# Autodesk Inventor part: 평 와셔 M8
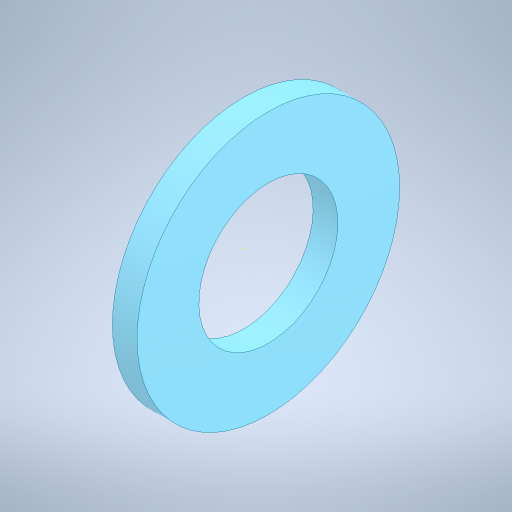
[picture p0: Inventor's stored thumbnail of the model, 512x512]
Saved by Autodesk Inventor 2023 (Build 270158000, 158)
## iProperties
Created: 2025-10
Part Number: 평 와셔 M8
Material: 강철, 연강
Description: 평면 와셔
Document SubType Name: Modeling
Designer: home
Density: 7.85 g/cm^3
Appearance: 기본값
Author: jhkim
Sending System: Autodesk Inventor 2026
Preprocessor: ST-DEVELOPER v20.1
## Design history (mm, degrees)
sketch "스케치1"
  geometry: 1 further point
  constraints: 1 other
feature "Solid1"
node "솔리드1"
